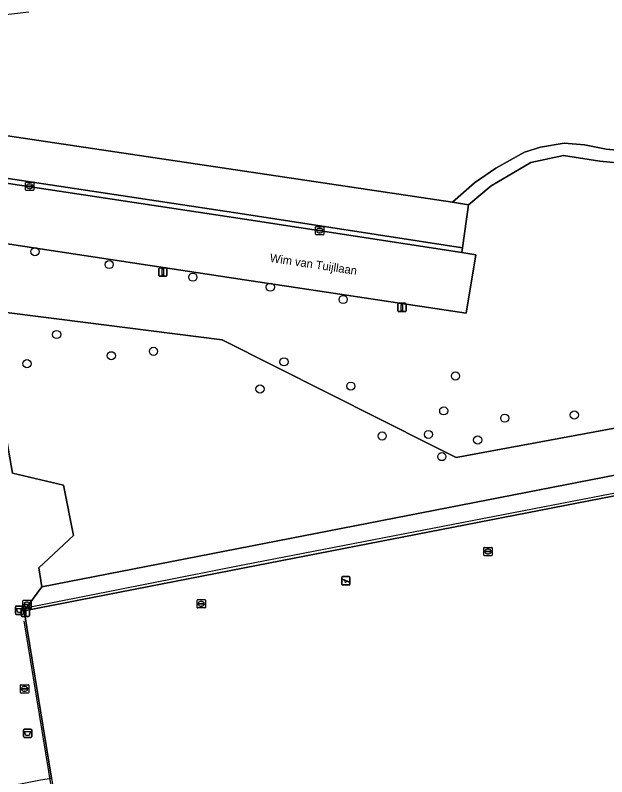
# Model space of a CAD drawing. Extents: x 160203 to 161530, y 379528 to 381797.
# Drawn here: x 160972.5 to 161043.5, y 380460.9 to 380552.4 of the extents above; entities that cross this region are included whole.
import ezdxf

# ---------------------------------------------------------------- set-up
doc = ezdxf.new("R2010")
doc.units = 0
for name, color, linetype in [('IMGEO_Afvalbak', 7, 'Continuous'), ('IMGEO_Boom', 7, 'Continuous'), ('IMGEO_Groenvoorziening', 7, 'Continuous'), ('IMGEO_Hek', 7, 'Continuous'), ('IMGEO_Kolk', 7, 'Continuous'), ('IMGEO_Lichtmast', 7, 'Continuous'), ('IMGEO_Loofbos', 7, 'Continuous'), ('IMGEO_Openbare_ruimte_label', 7, 'Continuous'), ('IMGEO_Parkeervlak_gesloten', 7, 'Continuous'), ('IMGEO_Rijbaan_lokaal_open', 7, 'Continuous'), ('IMGEO_Speelvoorziening', 7, 'Continuous'), ('IMGEO_Voetpad_halfverhard', 7, 'Continuous'), ('IMGEO_Voetpad_open', 7, 'Continuous'), ('IMGEO_Waterleidingput', 7, 'Continuous')]:
    doc.layers.add(name, color=color, linetype=linetype)

msp = doc.modelspace()

# ---------------------------------------------------------------- linework, layer by layer
at = {"layer": 'IMGEO_Afvalbak'}
for p, q in [((160972.51, 380480.5), (160972.51, 380481.3)), ((160972.51, 380481.3), (160972.51, 380480.5)), ((160972.61, 380481.4), (160973.4, 380481.4)), ((160973.4, 380481.4), (160972.61, 380481.4)), ((160973.5, 380481.3), (160973.5, 380480.5)), ((160973.5, 380480.5), (160973.5, 380481.3)), ((160973.4, 380480.4), (160972.61, 380480.4)), ((160972.61, 380480.4), (160973.4, 380480.4)), ((160973.476, 380465.714), (160973.476, 380466.514)), ((160973.476, 380466.514), (160973.476, 380465.714)), ((160973.576, 380466.614), (160974.366, 380466.614)), ((160974.366, 380466.614), (160973.576, 380466.614)), ((160974.466, 380466.514), (160974.466, 380465.714)), ((160974.466, 380465.714), (160974.466, 380466.514)), ((160974.366, 380465.614), (160973.576, 380465.614)), ((160973.576, 380465.614), (160974.366, 380465.614))]:
    msp.add_line(p, q, dxfattribs=at)
for points in [[(160972.653, 380481.114), (160973.357, 380481.114), (160973.208, 380480.644), (160972.802, 380480.644), (160972.653, 380481.114)], [(160973.619, 380466.328), (160974.323, 380466.328), (160974.174, 380465.858), (160973.768, 380465.858), (160973.619, 380466.328)]]:
    msp.add_lwpolyline(points, dxfattribs=at)
for centre, start, end in [((160972.61, 380481.3), 90, 180), ((160972.61, 380481.3), 90, 180), ((160973.4, 380481.3), 0, 90), ((160973.4, 380481.3), 360, 90), ((160972.61, 380480.5), 180, 270), ((160972.61, 380480.5), 180, 270), ((160973.4, 380480.5), 270, 0), ((160973.4, 380480.5), 270, 0), ((160973.576, 380466.514), 90, 180), ((160973.576, 380466.514), 90, 180), ((160973.576, 380465.714), 180, 270), ((160973.576, 380465.714), 180, 270), ((160974.366, 380466.514), 0, 90), ((160974.366, 380466.514), 360, 90), ((160974.366, 380465.714), 270, 0), ((160974.366, 380465.714), 270, 0)]:
    msp.add_arc(centre, 0.1, start, end, dxfattribs=at)
at = {"layer": 'IMGEO_Boom'}
for centre in [(160974.86, 380523.993), (160983.767, 380522.438), (160993.815, 380520.926), (161003.116, 380519.722), (161011.856, 380518.24), (160977.461, 380514.034), (160989.08, 380512.008), (160984.031, 380511.483), (160973.898, 380510.522), (161004.748, 380510.754), (161025.347, 380509.044), (161001.873, 380507.483), (161012.772, 380507.832), (161023.931, 380504.855), (161031.256, 380503.98), (161039.606, 380504.358), (161016.545, 380501.838), (161022.094, 380502.027), (161027.997, 380501.351), (161023.704, 380499.364)]:
    msp.add_circle(centre, 0.489, dxfattribs=at)
at = {"layer": 'IMGEO_Groenvoorziening'}
msp.add_lwpolyline([(160974.128, 380552.752), (160968.287, 380552.079), (160965.263, 380551.73), (160959.524, 380551.402), (160940.334, 380544.69), (160940.686, 380542.511), (161000, 380533.651), (161024.98, 380529.951), (161027.619, 380532.25), (161030.174, 380534.01), (161033.608, 380535.941), (161035.538, 380536.566), (161038.376, 380537.02), (161040.831, 380536.814), (161043.442, 380536.303), (161045.685, 380536.12)], dxfattribs=at)
for points in [[(161051.027, 380498.401), (161051.214, 380497.538), (161063.307, 380444.833), (161063.889, 380442.387), (161066.33, 380440.623), (161066.608, 380440.645), (161054.376, 380504.632), (161025.407, 380499.252), (161022.555, 380500.69), (160997.348, 380513.4), (160969.211, 380516.95), (160968.279, 380517.067), (160970.343, 380507.038), (160971.516, 380501.074), (160972.176, 380497.384), (160978.278, 380495.928), (160979.494, 380489.876), (160975.305, 380486.001), (160975.678, 380483.713)], [(161062.276, 380434.441), (161061.827, 380434.364), (161061.538, 380434.33), (161061.001, 380437.489), (161061.321, 380437.539), (161061.628, 380437.587), (161060.189, 380444.614), (161059.922, 380444.572), (161059.585, 380444.52), (161058.9, 380447.565), (161059.232, 380447.662), (161059.584, 380447.765), (161048.75, 380495.499), (161000, 380485.988), (160973.556, 380480.828), (160976.857, 380460.724), (160982.636, 380425.533), (160984.552, 380417.16), (160994.175, 380375.047), (160994.704, 380372.708), (160995.095, 380370.982), (161070.27, 380385.449)]]:
    msp.add_lwpolyline(points, close=True, dxfattribs=at)
at = {"layer": 'IMGEO_Hek'}
for points in [[(160997.348, 380513.4), (160969.211, 380516.95)], [(161054.376, 380504.632), (161025.407, 380499.252), (161022.555, 380500.69), (160997.348, 380513.4)], [(160973.317, 380481.104), (161000, 380486.406), (161045.364, 380495.173)], [(160984.282, 380417.109), (160982.444, 380425.328), (160973.565, 380479.625)]]:
    msp.add_lwpolyline(points, dxfattribs=at)
at = {"layer": 'IMGEO_Kolk'}
for p, q in [((160973.722, 380531.418), (160973.722, 380532.27)), ((160973.797, 380532.344), (160974.649, 380532.344)), ((160973.981, 380531.838), (160973.981, 380531.85)), ((160974.419, 380531.801), (160974.021, 380531.801)), ((160974.024, 380531.887), (160974.422, 380531.887)), ((160974.21, 380532.124), (160974.235, 380532.124)), ((160974.465, 380531.85), (160974.465, 380531.838)), ((160974.723, 380532.27), (160974.723, 380531.418)), ((160974.649, 380531.344), (160973.797, 380531.344)), ((160974.233, 380531.564), (160974.208, 380531.564)), ((161008.613, 380527.018), (161009.465, 380527.018)), ((161008.538, 380526.092), (161008.538, 380526.944)), ((161008.797, 380526.512), (161008.797, 380526.524)), ((161009.235, 380526.475), (161008.837, 380526.475)), ((161008.84, 380526.561), (161009.238, 380526.561)), ((161009.049, 380526.238), (161009.024, 380526.238)), ((161009.026, 380526.798), (161009.051, 380526.798)), ((161009.281, 380526.524), (161009.281, 380526.512)), ((161009.539, 380526.944), (161009.539, 380526.092)), ((161009.465, 380526.018), (161008.613, 380526.018)), ((160973.403, 380481.166), (160973.403, 380482.018)), ((160973.478, 380482.092), (160974.33, 380482.092)), ((160973.662, 380481.586), (160973.662, 380481.598)), ((160974.1, 380481.549), (160973.702, 380481.549)), ((160973.705, 380481.635), (160974.103, 380481.635)), ((160973.914, 380481.312), (160973.889, 380481.312)), ((160973.891, 380481.872), (160973.916, 380481.872)), ((160974.146, 380481.598), (160974.146, 380481.586)), ((160974.404, 380482.018), (160974.404, 380481.166)), ((160974.33, 380481.092), (160973.478, 380481.092)), ((160973.112, 380471.025), (160973.112, 380471.877)), ((160973.187, 380471.951), (160974.039, 380471.951)), ((160973.371, 380471.445), (160973.371, 380471.457)), ((160973.809, 380471.408), (160973.411, 380471.408)), ((160973.414, 380471.494), (160973.812, 380471.494)), ((160973.6, 380471.731), (160973.625, 380471.731)), ((160973.855, 380471.457), (160973.855, 380471.445)), ((160974.113, 380471.877), (160974.113, 380471.025)), ((160974.039, 380470.951), (160973.187, 380470.951)), ((160973.623, 380471.171), (160973.598, 380471.171))]:
    msp.add_line(p, q, dxfattribs=at)
for points in [[(160973.722, 380531.418), (160973.722, 380532.27)], [(160973.797, 380532.344), (160974.649, 380532.344)], [(160974.723, 380532.27), (160974.723, 380531.418)], [(160974.649, 380531.344), (160973.797, 380531.344)], [(161008.613, 380527.018), (161009.465, 380527.018)], [(161008.538, 380526.092), (161008.538, 380526.944)], [(161009.539, 380526.944), (161009.539, 380526.092)], [(161009.465, 380526.018), (161008.613, 380526.018)], [(160973.403, 380481.166), (160973.403, 380482.018)], [(160973.478, 380482.092), (160974.33, 380482.092)], [(160974.404, 380482.018), (160974.404, 380481.166)], [(160974.33, 380481.092), (160973.478, 380481.092)], [(160973.112, 380471.025), (160973.112, 380471.877)], [(160973.187, 380471.951), (160974.039, 380471.951)], [(160974.113, 380471.877), (160974.113, 380471.025)], [(160974.039, 380470.951), (160973.187, 380470.951)]]:
    msp.add_lwpolyline(points, dxfattribs=at)
for centre, radius, start, end in [((160973.799, 380532.268), 0.0765, 91.55205, 178.44795), ((160973.799, 380532.268), 0.0765, 91.55205, 178.44795), ((160974.021, 380531.847), 0.0403, 85.87752, 175.75265), ((160974.018, 380531.837), 0.0366, 178.93798, 274.71019), ((160974.422, 380531.844), 0.043, 264.86636, 352.45326), ((160974.426, 380531.849), 0.0386, 1.73085, 96.63898), ((160974.647, 380532.268), 0.0765, 1.55205, 88.44795), ((160974.647, 380532.268), 0.0765, 1.55205, 88.44795), ((160973.799, 380531.42), 0.0765, 181.55205, 268.44795), ((160973.799, 380531.42), 0.0765, 181.55205, 268.44795), ((160974.647, 380531.42), 0.0765, 271.55205, 358.44795), ((160974.647, 380531.42), 0.0765, 271.55205, 358.44795), ((161008.615, 380526.942), 0.0765, 91.55205, 178.44795), ((161008.615, 380526.942), 0.0765, 91.55205, 178.44795), ((161009.463, 380526.942), 0.0765, 1.55205, 88.44795), ((161009.463, 380526.942), 0.0765, 1.55205, 88.44795), ((161008.837, 380526.521), 0.0403, 85.87752, 175.75265), ((161008.834, 380526.511), 0.0366, 178.93798, 274.71019), ((161009.238, 380526.518), 0.043, 264.86636, 352.45326), ((161009.242, 380526.523), 0.0386, 1.73085, 96.63898), ((161008.615, 380526.094), 0.0765, 181.55205, 268.44795), ((161008.615, 380526.094), 0.0765, 181.55205, 268.44795), ((161009.463, 380526.094), 0.0765, 271.55205, 358.44795), ((161009.463, 380526.094), 0.0765, 271.55205, 358.44795), ((160973.48, 380482.016), 0.0765, 91.55205, 178.44795), ((160973.48, 380482.016), 0.0765, 91.55205, 178.44795), ((160973.702, 380481.595), 0.0403, 85.87752, 175.75265), ((160973.699, 380481.585), 0.0366, 178.93798, 274.71019), ((160974.103, 380481.592), 0.043, 264.86636, 352.45326), ((160974.107, 380481.597), 0.0386, 1.73085, 96.63898), ((160974.328, 380482.016), 0.0765, 1.55205, 88.44795), ((160974.328, 380482.016), 0.0765, 1.55205, 88.44795), ((160973.48, 380481.168), 0.0765, 181.55205, 268.44795), ((160973.48, 380481.168), 0.0765, 181.55205, 268.44795), ((160974.328, 380481.168), 0.0765, 271.55205, 358.44795), ((160974.328, 380481.168), 0.0765, 271.55205, 358.44795), ((160973.189, 380471.875), 0.0765, 91.55205, 178.44795), ((160973.189, 380471.875), 0.0765, 91.55205, 178.44795), ((160973.411, 380471.454), 0.0403, 85.87752, 175.75265), ((160973.408, 380471.444), 0.0366, 178.93798, 274.71019), ((160973.812, 380471.451), 0.043, 264.86636, 352.45326), ((160973.816, 380471.456), 0.0386, 1.73085, 96.63898), ((160974.037, 380471.875), 0.0765, 1.55205, 88.44795), ((160974.037, 380471.875), 0.0765, 1.55205, 88.44795), ((160973.189, 380471.027), 0.0765, 181.55205, 268.44795), ((160973.189, 380471.027), 0.0765, 181.55205, 268.44795), ((160974.037, 380471.027), 0.0765, 271.55205, 358.44795), ((160974.037, 380471.027), 0.0765, 271.55205, 358.44795)]:
    msp.add_arc(centre, radius, start, end, dxfattribs=at)
for centre, major_axis, ratio, start_param, end_param in [((160974.209, 380531.844), (-0.387, 0.002), 0.722429, 4.712389, 7.853982), ((160974.234, 380531.844), (-0.39, 0.002), 0.717154, 1.570796, 4.712389), ((161009.025, 380526.518), (-0.387, 0.002), 0.722429, 4.712389, 7.853982), ((161009.05, 380526.518), (-0.39, 0.002), 0.717154, 1.570796, 4.712389), ((160973.89, 380481.592), (-0.387, 0.002), 0.722429, 4.712389, 7.853982), ((160973.915, 380481.592), (-0.39, 0.002), 0.717154, 1.570796, 4.712389), ((160973.599, 380471.451), (-0.387, 0.002), 0.722429, 4.712389, 7.853982), ((160973.624, 380471.451), (-0.39, 0.002), 0.717154, 1.570796, 4.712389)]:
    msp.add_ellipse(centre, major_axis=major_axis, ratio=ratio, start_param=start_param, end_param=end_param, dxfattribs=at)
at = {"layer": 'IMGEO_Lichtmast'}
for p, q in [((160989.709, 380521.144), (160989.709, 380521.944)), ((160989.709, 380521.944), (160989.709, 380521.144)), ((160989.809, 380522.044), (160990.599, 380522.044)), ((160990.599, 380522.044), (160989.809, 380522.044)), ((160990.699, 380521.944), (160990.699, 380521.144)), ((160990.699, 380521.144), (160990.699, 380521.944)), ((160990.599, 380521.044), (160989.809, 380521.044)), ((160989.809, 380521.044), (160990.599, 380521.044)), ((161018.411, 380516.885), (161018.411, 380517.685)), ((161018.411, 380517.685), (161018.411, 380516.885)), ((161018.511, 380517.785), (161019.301, 380517.785)), ((161019.301, 380517.785), (161018.511, 380517.785)), ((161019.401, 380517.685), (161019.401, 380516.885)), ((161019.401, 380516.885), (161019.401, 380517.685)), ((161019.301, 380516.785), (161018.511, 380516.785)), ((161018.511, 380516.785), (161019.301, 380516.785)), ((160973.21, 380480.262), (160973.21, 380481.062)), ((160973.21, 380481.062), (160973.21, 380480.262)), ((160973.31, 380481.162), (160974.1, 380481.162)), ((160974.1, 380481.162), (160973.31, 380481.162)), ((160974.2, 380481.062), (160974.2, 380480.262)), ((160974.2, 380480.262), (160974.2, 380481.062)), ((160974.1, 380480.162), (160973.31, 380480.162)), ((160973.31, 380480.162), (160974.1, 380480.162))]:
    msp.add_line(p, q, dxfattribs=at)
for points in [[(160990.129, 380521.919), (160990.279, 380521.919), (160990.279, 380521.169), (160990.129, 380521.169), (160990.129, 380521.919)], [(161018.831, 380517.66), (161018.981, 380517.66), (161018.981, 380516.91), (161018.831, 380516.91), (161018.831, 380517.66)], [(160973.63, 380481.037), (160973.78, 380481.037), (160973.78, 380480.287), (160973.63, 380480.287), (160973.63, 380481.037)]]:
    msp.add_lwpolyline(points, dxfattribs=at)
for centre, start, end in [((160989.809, 380521.944), 90, 180), ((160989.809, 380521.944), 90, 180), ((160990.599, 380521.944), 0, 90), ((160990.599, 380521.944), 360, 90), ((160989.809, 380521.144), 180, 270), ((160989.809, 380521.144), 180, 270), ((160990.599, 380521.144), 270, 0), ((160990.599, 380521.144), 270, 0), ((161018.511, 380517.685), 90, 180), ((161018.511, 380517.685), 90, 180), ((161019.301, 380517.685), 0, 90), ((161019.301, 380517.685), 360, 90), ((161018.511, 380516.885), 180, 270), ((161018.511, 380516.885), 180, 270), ((161019.301, 380516.885), 270, 0), ((161019.301, 380516.885), 270, 0), ((160973.31, 380481.062), 90, 180), ((160973.31, 380481.062), 90, 180), ((160974.1, 380481.062), 0, 90), ((160974.1, 380481.062), 360, 90), ((160973.31, 380480.262), 180, 270), ((160973.31, 380480.262), 180, 270), ((160974.1, 380480.262), 270, 0), ((160974.1, 380480.262), 270, 0)]:
    msp.add_arc(centre, 0.1, start, end, dxfattribs=at)
at = {"layer": 'IMGEO_Loofbos'}
msp.add_lwpolyline([(161068.738, 380524.054), (161069.501, 380528.085), (161050.647, 380530.954), (161050.169, 380536.216), (161045.973, 380534.533), (161042.657, 380534.867), (161038.31, 380535.563), (161034.399, 380534.694), (161029.618, 380531.911), (161026.899, 380529.633), (161026.173, 380524.441), (161026.094, 380523.879), (161027.779, 380523.619), (161026.638, 380516.587), (161000, 380520.618), (160970.441, 380525.091), (160969.211, 380516.95), (160997.348, 380513.4), (161022.555, 380500.69), (161025.407, 380499.252), (161054.376, 380504.632), (161054.068, 380506.244), (161055.556, 380506.056), (161065.849, 380508.788)], close=True, dxfattribs=at)
at = {"layer": 'IMGEO_Parkeervlak_gesloten'}
msp.add_lwpolyline([(161024.98, 380529.951), (161000, 380533.651), (160940.686, 380542.511), (160845.744, 380556.692), (160833.175, 380558.569), (160830.154, 380559), (160828.405, 380559.25), (160827.637, 380559.36), (160827.221, 380554.627), (160828.18, 380554.482), (161000, 380528.513), (161026.173, 380524.441), (161026.899, 380529.633)], close=True, dxfattribs=at)
at = {"layer": 'IMGEO_Rijbaan_lokaal_open'}
for points in [[(161026.173, 380524.441), (161000, 380528.513), (160828.18, 380554.482), (160828.089, 380553.895), (161000, 380527.913), (161026.094, 380523.879)], [(160826.75, 380554.296), (160826.76, 380553.818), (160825.987, 380548.612), (160825.841, 380547.097), (160831.991, 380546.196), (160911.436, 380534.021), (160965.031, 380525.91), (160970.441, 380525.091), (161000, 380520.618), (161026.638, 380516.587), (161027.779, 380523.619), (161026.094, 380523.879), (161000, 380527.913), (160828.089, 380553.895)]]:
    msp.add_lwpolyline(points, close=True, dxfattribs=at)
at = {"layer": 'IMGEO_Speelvoorziening'}
for p, q in [((161011.782, 380484.937), (161012.572, 380484.937)), ((161012.572, 380484.937), (161011.782, 380484.937)), ((161011.682, 380484.037), (161011.682, 380484.837)), ((161011.682, 380484.837), (161011.682, 380484.037)), ((161012.065, 380484.465), (161011.726, 380484.602)), ((161011.751, 380484.662), (161012.627, 380484.309)), ((161012.603, 380484.249), (161012.263, 380484.386)), ((161012.672, 380484.837), (161012.672, 380484.037)), ((161012.672, 380484.037), (161012.672, 380484.837)), ((161012.572, 380483.937), (161011.782, 380483.937)), ((161011.782, 380483.937), (161012.572, 380483.937))]:
    msp.add_line(p, q, dxfattribs=at)
for centre, radius, start, end in [((161011.782, 380484.837), 0.1, 90, 180), ((161011.782, 380484.837), 0.1, 90, 180), ((161012.572, 380484.837), 0.1, 0, 90), ((161012.572, 380484.837), 0.1, 360, 90), ((161011.782, 380484.037), 0.1, 180, 270), ((161011.782, 380484.037), 0.1, 180, 270), ((161011.739, 380484.632), 0.0327, 68.07798, 248.07798), ((161012.144, 380484.375), 0.12, 130.99278, 5.16318), ((161012.572, 380484.037), 0.1, 270, 0), ((161012.572, 380484.037), 0.1, 270, 0), ((161012.615, 380484.279), 0.0327, 248.07798, 68.07798)]:
    msp.add_arc(centre, radius, start, end, dxfattribs=at)
at = {"layer": 'IMGEO_Voetpad_halfverhard'}
msp.add_lwpolyline([(161034.399, 380534.694), (161038.31, 380535.563), (161042.657, 380534.867), (161045.973, 380534.533), (161050.169, 380536.216), (161050.001, 380538.062), (161048.145, 380536.889), (161045.685, 380536.12), (161043.442, 380536.303), (161040.831, 380536.814), (161038.376, 380537.02), (161035.538, 380536.566), (161033.608, 380535.941), (161030.174, 380534.01), (161027.619, 380532.25), (161024.98, 380529.951), (161026.899, 380529.633), (161029.618, 380531.911)], close=True, dxfattribs=at)
at = {"layer": 'IMGEO_Voetpad_open'}
for points in [[(160979.494, 380489.876), (160978.278, 380495.928), (160972.176, 380497.384), (160971.516, 380501.074), (160970.343, 380507.038), (160968.279, 380517.067), (160963.792, 380517.634), (160954.687, 380518.782), (160953.58, 380518.922), (160951.934, 380519.13), (160954.812, 380504.084), (160946.869, 380502.452), (160947.345, 380500), (160956.686, 380451.885), (160959.623, 380452.431), (160964.41, 380458.399), (160970.636, 380459.579), (160975.531, 380460.507), (160976.857, 380460.724), (160973.556, 380480.828), (160975.678, 380483.713), (160975.305, 380486.001)], [(161066.608, 380440.645), (161066.33, 380440.623), (161063.889, 380442.387), (161063.307, 380444.833), (161051.214, 380497.538), (161051.027, 380498.401), (160975.678, 380483.713), (160973.556, 380480.828), (161000, 380485.988), (161048.75, 380495.499), (161049.197, 380495.587), (161061.752, 380440.973), (161070.159, 380389.115), (161070.672, 380385.946), (161073.03, 380386.405), (161065.777, 380431.153), (161064.915, 380436.574), (161066.501, 380438.673), (161066.978, 380438.71)]]:
    msp.add_lwpolyline(points, close=True, dxfattribs=at)
at = {"layer": 'IMGEO_Waterleidingput'}
for p, q in [((161028.742, 380487.532), (161028.742, 380488.384)), ((161028.817, 380488.458), (161029.669, 380488.458)), ((161029.001, 380487.952), (161029.001, 380487.964)), ((161029.439, 380487.915), (161029.041, 380487.915)), ((161029.044, 380488.001), (161029.442, 380488.001)), ((161029.253, 380487.678), (161029.228, 380487.678)), ((161029.23, 380488.238), (161029.255, 380488.238)), ((161029.485, 380487.964), (161029.485, 380487.952)), ((161029.743, 380488.384), (161029.743, 380487.532)), ((161029.669, 380487.458), (161028.817, 380487.458)), ((160994.321, 380481.246), (160994.321, 380482.098)), ((160994.396, 380482.172), (160995.248, 380482.172)), ((160994.58, 380481.666), (160994.58, 380481.678)), ((160995.018, 380481.629), (160994.62, 380481.629)), ((160994.623, 380481.715), (160995.021, 380481.715)), ((160994.832, 380481.392), (160994.807, 380481.392)), ((160994.809, 380481.952), (160994.834, 380481.952)), ((160995.064, 380481.678), (160995.064, 380481.666)), ((160995.322, 380482.098), (160995.322, 380481.246)), ((160995.248, 380481.172), (160994.396, 380481.172))]:
    msp.add_line(p, q, dxfattribs=at)
for points in [[(161028.742, 380487.532), (161028.742, 380488.384)], [(161028.817, 380488.458), (161029.669, 380488.458)], [(161029.743, 380488.384), (161029.743, 380487.532)], [(161029.669, 380487.458), (161028.817, 380487.458)], [(160994.321, 380481.246), (160994.321, 380482.098)], [(160994.396, 380482.172), (160995.248, 380482.172)], [(160995.322, 380482.098), (160995.322, 380481.246)], [(160995.248, 380481.172), (160994.396, 380481.172)]]:
    msp.add_lwpolyline(points, dxfattribs=at)
for centre, radius, start, end in [((161028.819, 380488.382), 0.0765, 91.55205, 178.44795), ((161028.819, 380488.382), 0.0765, 91.55205, 178.44795), ((161029.041, 380487.961), 0.0403, 85.87752, 175.75265), ((161029.038, 380487.951), 0.0366, 178.93798, 274.71019), ((161029.442, 380487.958), 0.043, 264.86636, 352.45326), ((161029.446, 380487.963), 0.0386, 1.73085, 96.63898), ((161029.667, 380488.382), 0.0765, 1.55205, 88.44795), ((161029.667, 380488.382), 0.0765, 1.55205, 88.44795), ((161028.819, 380487.534), 0.0765, 181.55205, 268.44795), ((161028.819, 380487.534), 0.0765, 181.55205, 268.44795), ((161029.667, 380487.534), 0.0765, 271.55205, 358.44795), ((161029.667, 380487.534), 0.0765, 271.55205, 358.44795), ((160994.398, 380482.096), 0.0765, 91.55205, 178.44795), ((160994.398, 380482.096), 0.0765, 91.55205, 178.44795), ((160994.62, 380481.675), 0.0403, 85.87752, 175.75265), ((160994.617, 380481.665), 0.0366, 178.93798, 274.71019), ((160995.021, 380481.672), 0.043, 264.86636, 352.45326), ((160995.025, 380481.677), 0.0386, 1.73085, 96.63898), ((160995.246, 380482.096), 0.0765, 1.55205, 88.44795), ((160995.246, 380482.096), 0.0765, 1.55205, 88.44795), ((160994.398, 380481.248), 0.0765, 181.55205, 268.44795), ((160994.398, 380481.248), 0.0765, 181.55205, 268.44795), ((160995.246, 380481.248), 0.0765, 271.55205, 358.44795), ((160995.246, 380481.248), 0.0765, 271.55205, 358.44795)]:
    msp.add_arc(centre, radius, start, end, dxfattribs=at)
for centre, major_axis, ratio, start_param, end_param in [((161029.229, 380487.958), (-0.387, 0.002), 0.722429, 4.712389, 7.853982), ((161029.254, 380487.958), (-0.39, 0.002), 0.717154, 1.570796, 4.712389), ((160994.808, 380481.672), (-0.387, 0.002), 0.722429, 4.712389, 7.853982), ((160994.833, 380481.672), (-0.39, 0.002), 0.717154, 1.570796, 4.712389)]:
    msp.add_ellipse(centre, major_axis=major_axis, ratio=ratio, start_param=start_param, end_param=end_param, dxfattribs=at)

# ---------------------------------------------------------------- texts
at = {"layer": 'IMGEO_Openbare_ruimte_label'}
msp.add_text('Wim van Tuijllaan', height=1, rotation=351.37577, dxfattribs=at).set_placement((161003.002, 380522.776))

doc.saveas('drawing.dxf')
